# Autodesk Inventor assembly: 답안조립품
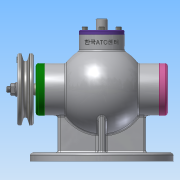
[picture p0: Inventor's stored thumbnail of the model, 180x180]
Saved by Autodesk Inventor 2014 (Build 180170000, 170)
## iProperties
Created: 2020-08
Part Number: 답안조립품
Document SubType Name: Assembly
Designer: kb542
Author: kb542
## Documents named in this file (18)
- C:\Users\kb542\Desktop\700806V1005\답안조립품.iam
- C:\Users\kb542\Desktop\700806V1005\본체.ipt
- C:\Users\kb542\Desktop\700806V1005\V-벨트풀리.ipt
- C:\Users\kb542\Desktop\700806V1005\너트 M8.ipt
- C:\Users\kb542\Desktop\700806V1005\뒤커버.ipt
- C:\Users\kb542\Desktop\700806V1005\멈춤링 15x1.ipt
- C:\Users\kb542\Desktop\700806V1005\멈춤링 35x1.6.ipt
- 멈춤링 35x1.6.ipt
- C:\Users\kb542\Desktop\700806V1005\베어링 6202.ipt
- 베어링 6202.ipt
- C:\Users\kb542\Desktop\700806V1005\볼트 M4.ipt
- C:\Users\kb542\Desktop\700806V1005\상부커버.ipt
- C:\Users\kb542\Desktop\700806V1005\슬라이드.ipt
- C:\Users\kb542\Desktop\700806V1005\앞커버.ipt
- C:\Users\kb542\Desktop\700806V1005\오일 실 15 30 7.ipt
- C:\Users\kb542\Desktop\700806V1005\칼라.ipt
- C:\Users\kb542\Desktop\700806V1005\키 3x3x12.ipt
- C:\Users\kb542\Desktop\700806V1005\편심축.ipt
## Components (1 placed, 1 different names)
1. V-벨트풀리:1
